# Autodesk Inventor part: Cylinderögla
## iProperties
Created: 2001-12
Part Number: Cylinderögla
Material: S235JRG2
Document SubType Name: Modeling
Designer: Tobben
Control State: 0
Master: False
Checked Out: False
Shininess: 64.0
Length Units: 11269
Angle Units: 11279
Time Units: 11290
Mass Units: 11283
Length Display Precision: 3
Angle Display Precision: 2
Compacted: True
Density: 0.0
Volumn: 0.0
Area: 0.0
PropertySet Name: Model Information
Author: Tobben
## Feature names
1. Extrusion1
2. Extrusion2
3. Extrusion3
